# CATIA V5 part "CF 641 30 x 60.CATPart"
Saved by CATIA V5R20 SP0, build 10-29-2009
Part number: CF 641 30 x 60
Definition: NONE
Nomenclature: CF 641 30 x 60
Source: Unknown
Description: CF 641 30 x 60
Bounding box of the stored display mesh (mm): x -34 to 26, y -26.5 to 26.5, z -26.5 to 26.5
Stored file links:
  C:\Users\Utente\Desktop\IO LAVORO\3D X SITO CF\X SITO\CF 641\CF 641 30 x 60.CATPart
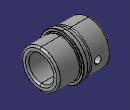
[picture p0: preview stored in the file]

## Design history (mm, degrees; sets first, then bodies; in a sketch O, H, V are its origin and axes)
Body1 "CF 641 30 x 60" (main body)
  Solid1: solid without history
